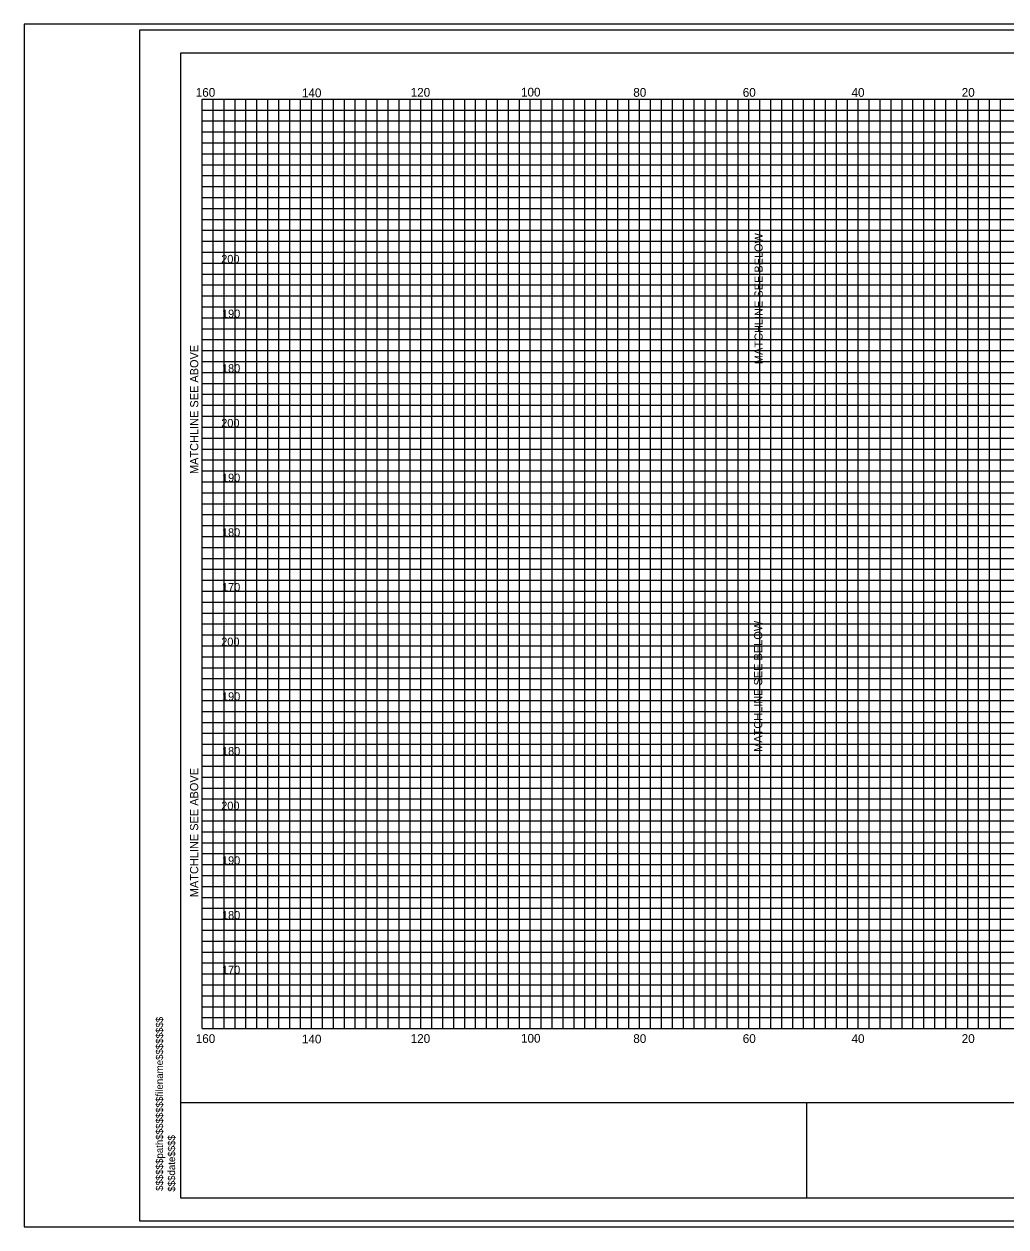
# Model space of a CAD drawing. Extents: x 967 to 1623, y 964 to 7064.
# Drawn here: x 967.4 to 1147, y 1803.7 to 2023.7 of the extents above; entities that cross this region are included whole.
import ezdxf

# ---------------------------------------------------------------- set-up
doc = ezdxf.new("R2010")
doc.units = 0
for name, color, linetype in [('Default', 7, 'Continuous'), ('RD_SHT_Bndy', 7, 'Continuous'), ('RD_SHT_IplotShp', 7, 'Continuous'), ('RD_SHT_MjGrid', 7, 'Continuous'), ('RD_SHT_MnGrid', 7, 'Continuous'), ('RD_SHT_TX', 7, 'Continuous'), ('RD_Sketch1', 7, 'Continuous'), ('RD_XS_TX_Station', 7, 'Continuous')]:
    doc.layers.add(name, color=color, linetype=linetype)

msp = doc.modelspace()

# ---------------------------------------------------------------- linework, layer by layer
at = {"layer": 'RD_SHT_Bndy'}
for p, q in [((996.11, 1808.98), (996.11, 2018.46)), ((996.11, 2018.46), (1323.89, 2018.46)), ((996.11, 1826.49), (1323.89, 1826.49)), ((1110.59, 1808.98), (1110.59, 1826.56)), ((1323.89, 1808.98), (996.11, 1808.98))]:
    msp.add_line(p, q, dxfattribs=at)
at = {"layer": 'RD_SHT_IplotShp'}
for points in [[(967.41, 1803.72), (1326.28, 1803.72), (1326.28, 2023.72), (967.41, 2023.72)], [(988.52, 1804.84), (1326.28, 1804.84), (1326.28, 2022.6), (988.52, 2022.6)]]:
    msp.add_lwpolyline(points, close=True, dxfattribs=at)
at = {"layer": 'RD_SHT_MjGrid'}
for p, q in [((1000, 2010), (1320, 2010)), ((1000, 1840), (1000, 2010)), ((1010, 1840), (1010, 2010)), ((1020, 1840), (1020, 2010)), ((1030, 1840), (1030, 2010)), ((1040, 1840), (1040, 2010)), ((1050, 1840), (1050, 2010)), ((1060, 1840), (1060, 2010)), ((1070, 1840), (1070, 2010)), ((1080, 1840), (1080, 2010)), ((1090, 1840), (1090, 2010)), ((1100, 1840), (1100, 2010)), ((1110, 1840), (1110, 2010)), ((1120, 1840), (1120, 2010)), ((1130, 1840), (1130, 2010)), ((1140, 1840), (1140, 2010)), ((1000, 2000), (1320, 2000)), ((1000, 1990), (1320, 1990)), ((1000, 1980), (1320, 1980)), ((1000, 1970), (1320, 1970)), ((1000, 1960), (1320, 1960)), ((1000, 1950), (1320, 1950)), ((1000, 1940), (1320, 1940)), ((1000, 1930), (1320, 1930)), ((1000, 1920), (1320, 1920)), ((1000, 1910), (1320, 1910)), ((1000, 1900), (1320, 1900)), ((1000, 1890), (1320, 1890)), ((1000, 1880), (1320, 1880)), ((1000, 1870), (1320, 1870)), ((1000, 1860), (1320, 1860)), ((1000, 1850), (1320, 1850)), ((1000, 1840), (1320, 1840))]:
    msp.add_line(p, q, dxfattribs=at)
at = {"layer": 'RD_SHT_MnGrid'}
for p, q in [((1002, 1840), (1002, 2010)), ((1004, 1840), (1004, 2010)), ((1006, 1840), (1006, 2010)), ((1008, 1840), (1008, 2010)), ((1012, 1840), (1012, 2010)), ((1014, 1840), (1014, 2010)), ((1016, 1840), (1016, 2010)), ((1018, 1840), (1018, 2010)), ((1022, 1840), (1022, 2010)), ((1024, 1840), (1024, 2010)), ((1026, 1840), (1026, 2010)), ((1028, 1840), (1028, 2010)), ((1032, 1840), (1032, 2010)), ((1034, 1840), (1034, 2010)), ((1036, 1840), (1036, 2010)), ((1038, 1840), (1038, 2010)), ((1042, 1840), (1042, 2010)), ((1044, 1840), (1044, 2010)), ((1046, 1840), (1046, 2010)), ((1048, 1840), (1048, 2010)), ((1052, 1840), (1052, 2010)), ((1054, 1840), (1054, 2010)), ((1056, 1840), (1056, 2010)), ((1058, 1840), (1058, 2010)), ((1062, 1840), (1062, 2010)), ((1064, 1840), (1064, 2010)), ((1066, 1840), (1066, 2010)), ((1068, 1840), (1068, 2010)), ((1072, 1840), (1072, 2010)), ((1074, 1840), (1074, 2010)), ((1076, 1840), (1076, 2010)), ((1078, 1840), (1078, 2010)), ((1082, 1840), (1082, 2010)), ((1084, 1840), (1084, 2010)), ((1086, 1840), (1086, 2010)), ((1088, 1840), (1088, 2010)), ((1092, 1840), (1092, 2010)), ((1094, 1840), (1094, 2010)), ((1096, 1840), (1096, 2010)), ((1098, 1840), (1098, 2010)), ((1102, 1840), (1102, 2010)), ((1104, 1840), (1104, 2010)), ((1106, 1840), (1106, 2010)), ((1108, 1840), (1108, 2010)), ((1112, 1840), (1112, 2010)), ((1114, 1840), (1114, 2010)), ((1116, 1840), (1116, 2010)), ((1118, 1840), (1118, 2010)), ((1122, 1840), (1122, 2010)), ((1124, 1840), (1124, 2010)), ((1126, 1840), (1126, 2010)), ((1128, 1840), (1128, 2010)), ((1132, 1840), (1132, 2010)), ((1134, 1840), (1134, 2010)), ((1136, 1840), (1136, 2010)), ((1138, 1840), (1138, 2010)), ((1142, 1840), (1142, 2010)), ((1144, 1840), (1144, 2010)), ((1146, 1840), (1146, 2010)), ((1000, 2008), (1320, 2008)), ((1000, 2006), (1320, 2006)), ((1000, 2004), (1320, 2004)), ((1000, 2002), (1320, 2002)), ((1000, 1998), (1320, 1998)), ((1000, 1996), (1320, 1996)), ((1000, 1994), (1320, 1994)), ((1000, 1992), (1320, 1992)), ((1000, 1988), (1320, 1988)), ((1000, 1986), (1320, 1986)), ((1000, 1984), (1320, 1984)), ((1000, 1982), (1320, 1982)), ((1000, 1978), (1320, 1978)), ((1000, 1976), (1320, 1976)), ((1000, 1974), (1320, 1974)), ((1000, 1972), (1320, 1972)), ((1000, 1968), (1320, 1968)), ((1000, 1966), (1320, 1966)), ((1000, 1964), (1320, 1964)), ((1000, 1962), (1320, 1962)), ((1000, 1958), (1320, 1958)), ((1000, 1956), (1320, 1956)), ((1000, 1954), (1320, 1954)), ((1000, 1952), (1320, 1952)), ((1000, 1948), (1320, 1948)), ((1000, 1946), (1320, 1946)), ((1000, 1944), (1320, 1944)), ((1000, 1942), (1320, 1942)), ((1000, 1938), (1320, 1938)), ((1000, 1936), (1320, 1936)), ((1000, 1934), (1320, 1934)), ((1000, 1932), (1320, 1932)), ((1000, 1928), (1320, 1928)), ((1000, 1926), (1320, 1926)), ((1000, 1924), (1320, 1924)), ((1000, 1922), (1320, 1922)), ((1000, 1918), (1320, 1918)), ((1000, 1916), (1320, 1916)), ((1000, 1914), (1320, 1914)), ((1000, 1912), (1320, 1912)), ((1000, 1908), (1320, 1908)), ((1000, 1906), (1320, 1906)), ((1000, 1904), (1320, 1904)), ((1000, 1902), (1320, 1902)), ((1000, 1898), (1320, 1898)), ((1000, 1896), (1320, 1896)), ((1000, 1894), (1320, 1894)), ((1000, 1892), (1320, 1892)), ((1000, 1888), (1320, 1888)), ((1000, 1886), (1320, 1886)), ((1000, 1884), (1320, 1884)), ((1000, 1882), (1320, 1882)), ((1000, 1878), (1320, 1878)), ((1000, 1876), (1320, 1876)), ((1000, 1874), (1320, 1874)), ((1000, 1872), (1320, 1872)), ((1000, 1868), (1320, 1868)), ((1000, 1866), (1320, 1866)), ((1000, 1864), (1320, 1864)), ((1000, 1862), (1320, 1862)), ((1000, 1858), (1320, 1858)), ((1000, 1856), (1320, 1856)), ((1000, 1854), (1320, 1854)), ((1000, 1852), (1320, 1852)), ((1000, 1848), (1320, 1848)), ((1000, 1846), (1320, 1846)), ((1000, 1844), (1320, 1844)), ((1000, 1842), (1320, 1842))]:
    msp.add_line(p, q, dxfattribs=at)
at = {"layer": 'RD_Sketch1'}
msp.add_lwpolyline([(967.41, 1803.72), (1326.28, 1803.72), (1326.28, 2023.72), (967.41, 2023.72)], close=True, dxfattribs=at)
at = {"layer": 'RD_XS_TX_Station'}
for p, q in [((1100, 1960), (1100, 2010)), ((1100, 1880), (1100, 1930))]:
    msp.add_line(p, q, dxfattribs=at)

# ---------------------------------------------------------------- texts
at = {"layer": 'Default'}
for s, p in [('200', (1003.47, 1980)), ('190', (1003.61, 1970)), ('180', (1003.61, 1960)), ('200', (1003.47, 1950)), ('190', (1003.61, 1940)), ('180', (1003.61, 1930)), ('170', (1003.61, 1920)), ('200', (1003.47, 1910)), ('190', (1003.61, 1900)), ('180', (1003.61, 1890)), ('200', (1003.47, 1880)), ('190', (1003.61, 1870)), ('180', (1003.61, 1860)), ('170', (1003.61, 1850))]:
    msp.add_text(s, height=1.5, dxfattribs=at).set_placement(p)
for s, p in [('$$$$$$path$$$$$$$$filename$$$$$$$$', (992.83, 1810.31)), ('$$$date$$$$', (995.04, 1810.17))]:
    msp.add_text(s, height=1.3258, rotation=90, dxfattribs=at).set_placement(p)
at = {"layer": 'RD_SHT_TX'}
for s, p in [('160', (998.81, 2010.42)), ('140', (1018.23, 2010.34)), ('120', (1038.12, 2010.43)), ('100', (1058.3, 2010.47)), ('80', (1078.84, 2010.42)), ('60', (1098.86, 2010.42)), ('40', (1118.75, 2010.41)), ('20', (1138.91, 2010.42)), ('160', (998.81, 1837.37)), ('140', (1018.23, 1837.29)), ('120', (1038.12, 1837.38)), ('100', (1058.3, 1837.42)), ('80', (1078.84, 1837.37)), ('60', (1098.86, 1837.37)), ('40', (1118.75, 1837.36)), ('20', (1138.91, 1837.37))]:
    msp.add_text(s, height=1.6, dxfattribs=at).set_placement(p)
at = {"layer": 'RD_XS_TX_Station'}
for s, p in [('MATCHLINE SEE BELOW', (1102.51, 1961.53)), ('MATCHLINE SEE ABOVE', (999.28, 1941.42)), ('MATCHLINE SEE BELOW', (1102.42, 1890.61)), ('MATCHLINE SEE ABOVE', (999.26, 1864.03))]:
    msp.add_text(s, height=1.5, rotation=90, dxfattribs=at).set_placement(p)

doc.saveas('drawing.dxf')
